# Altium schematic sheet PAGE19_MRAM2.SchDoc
size 381 x 381 mm; SheetNumber: 20; SheetTotal: 28
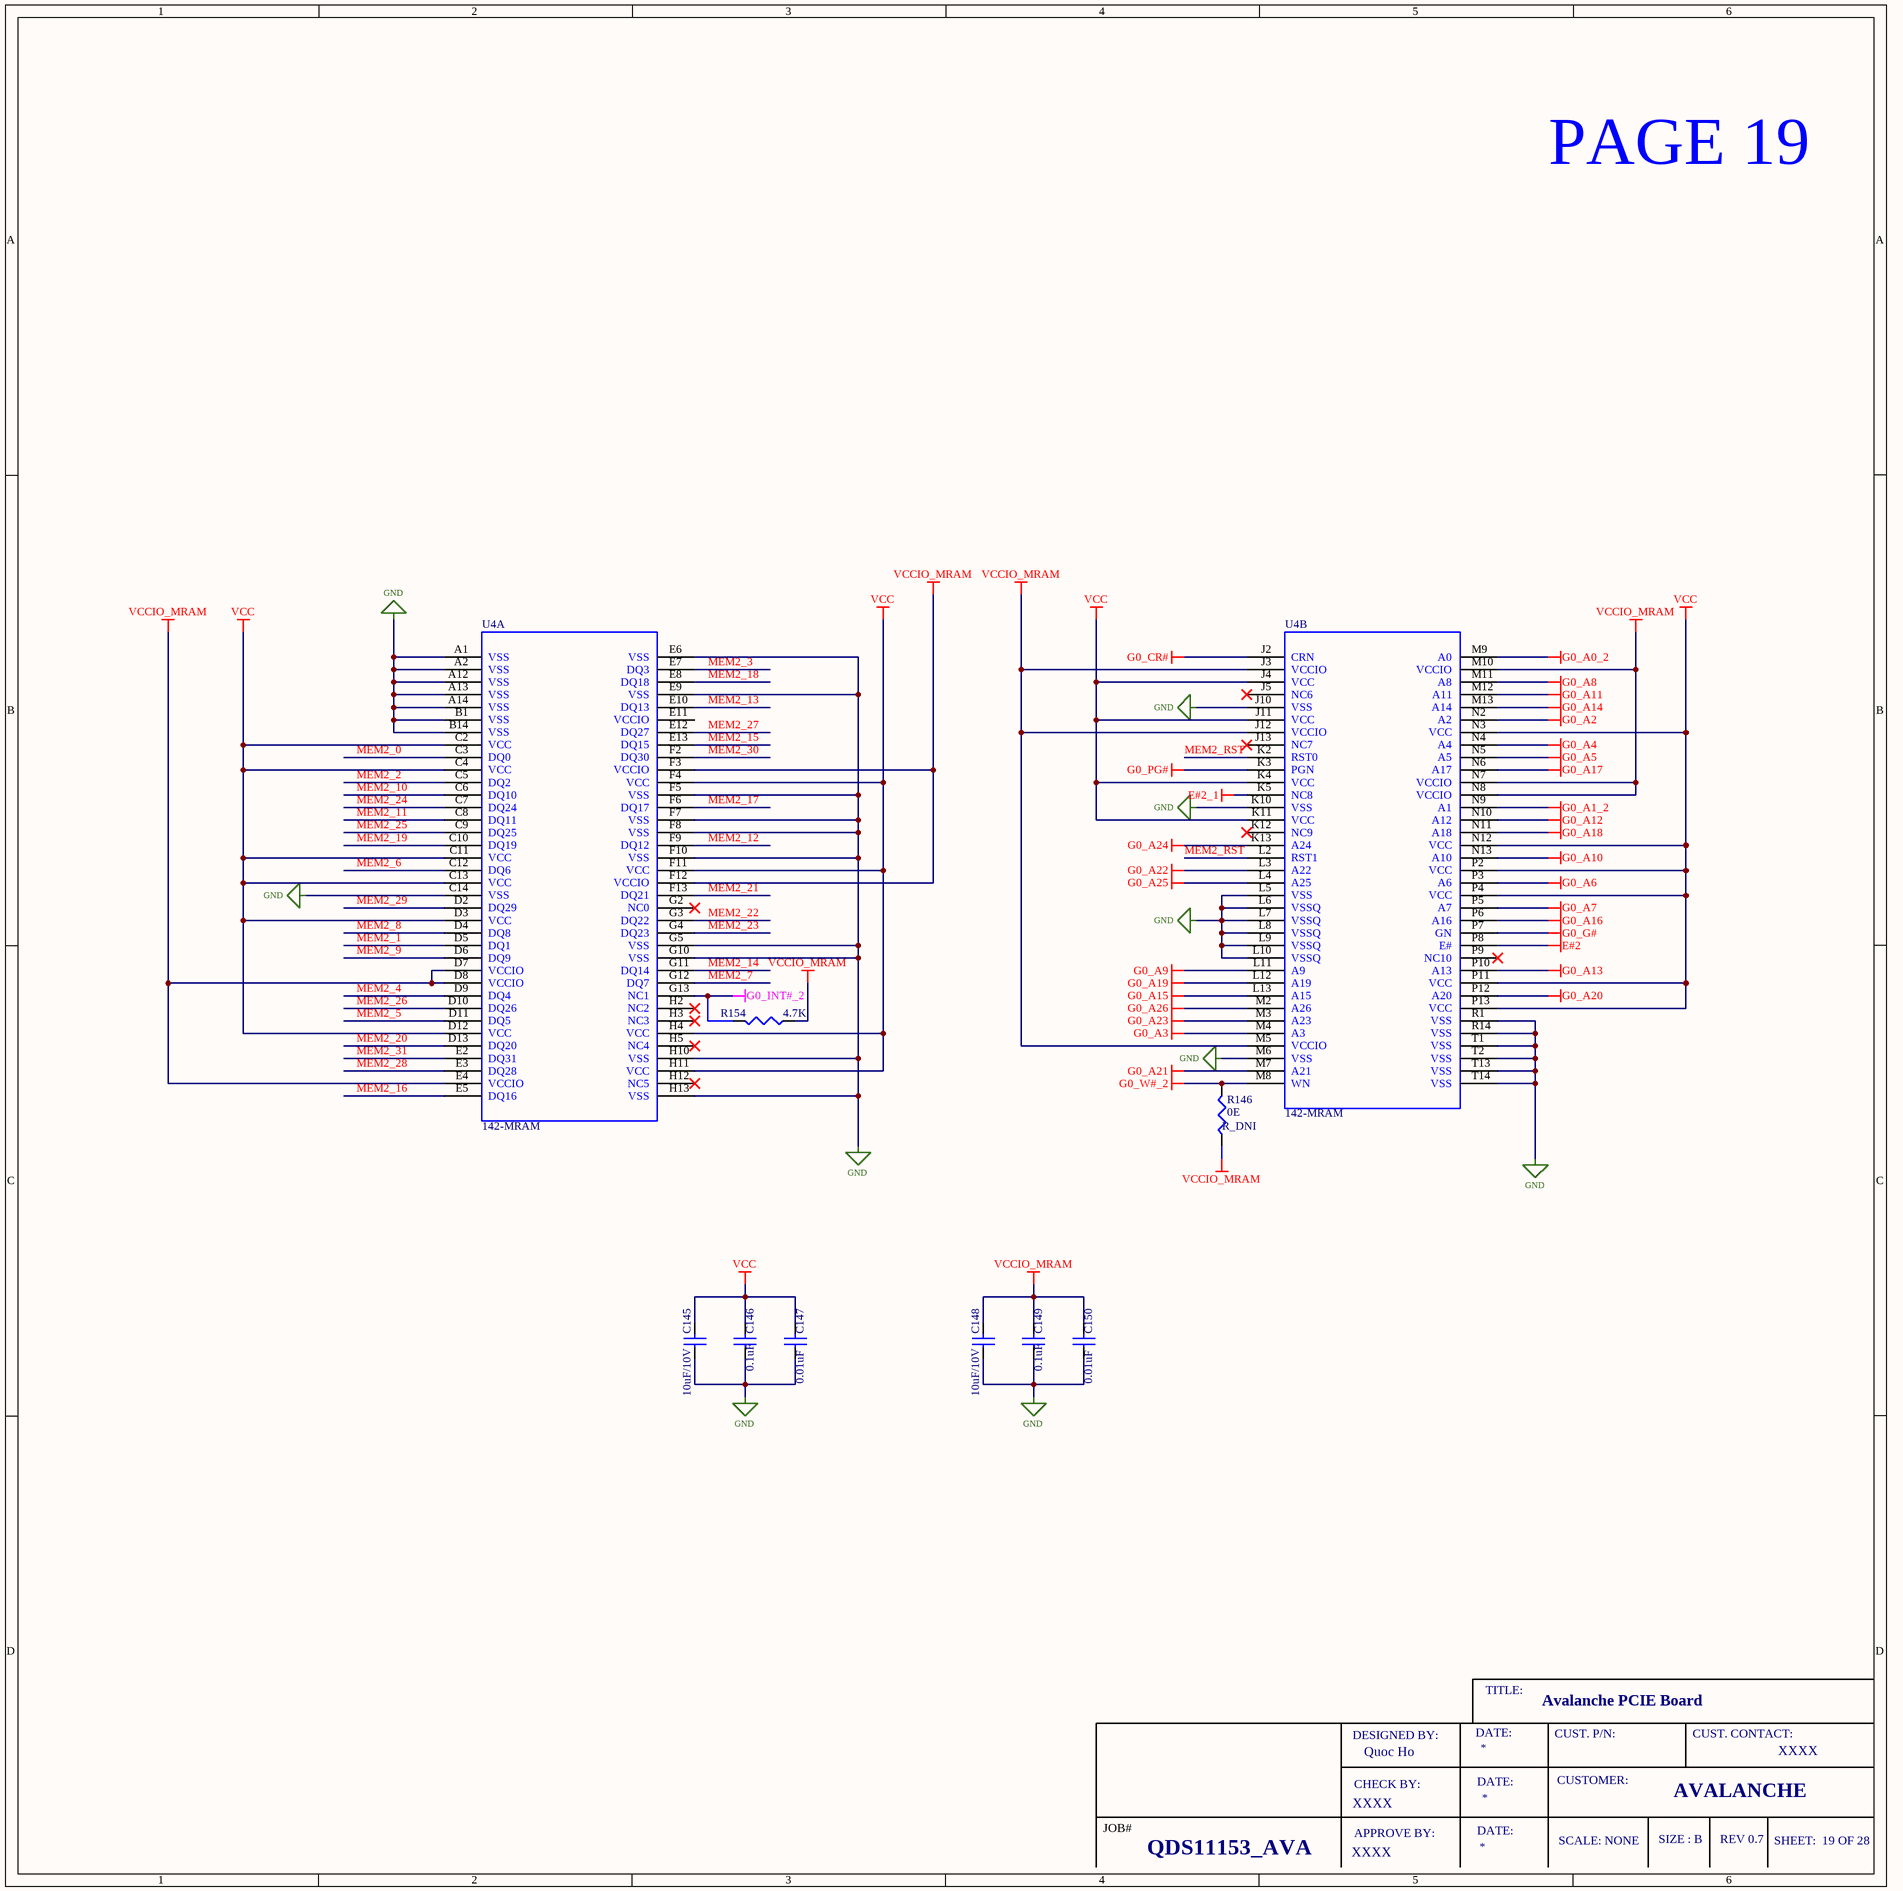
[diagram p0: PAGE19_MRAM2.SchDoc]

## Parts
C145  10uF/10V  [CN_0402]
C146  0.1uF  [CN_0402]
C147  0.01uF  [CN_0402]
C148  10uF/10V  [CN_0402]
C149  0.1uF  [CN_0402]
C150  0.01uF  [CN_0402]
R146  0E  [RN_0402]
R154  4.7K  [RN_0402]
U4  142-MRAM  [142-MRAM]  (parts A,B of 2)

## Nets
E#2: U4.P8(E#)
E#2_1: U4.K5(NC8)
G0_A0_2: U4.M9(A0)
G0_A1_2: U4.N9(A1)
G0_A2: U4.N2(A2)
G0_A3: U4.M4(A3)
G0_A4: U4.N4(A4)
G0_A5: U4.N5(A5)
G0_A6: U4.P3(A6)
G0_A7: U4.P5(A7)
G0_A8: U4.M11(A8)
G0_A9: U4.L11(A9)
G0_A10: U4.N13(A10)
G0_A11: U4.M12(A11)
G0_A12: U4.N10(A12)
G0_A13: U4.P10(A13)
G0_A14: U4.M13(A14)
G0_A15: U4.L13(A15)
G0_A16: U4.P6(A16)
G0_A17: U4.N6(A17)
G0_A18: U4.N11(A18)
G0_A19: U4.L12(A19)
G0_A20: U4.P12(A20)
G0_A21: U4.M7(A21)
G0_A22: U4.L3(A22)
G0_A23: U4.M3(A23)
G0_A24: U4.K13(A24)
G0_A25: U4.L4(A25)
G0_A26: U4.M2(A26)
G0_CR#: U4.J2(CRN)
G0_G#: U4.P7(GN)
G0_INT#_2: R154.2 U4.G13(NC1)
G0_PG#: U4.K3(PGN)
G0_W#_2: R146.2 U4.M8(WN)
GND: C145.1 C146.1 C147.1 C148.1 C149.1 C150.1 U4.A1(VSS) U4.A2(VSS) U4.A12(VSS) U4.A13(VSS) U4.A14(VSS) U4.B1(VSS) U4.B14(VSS) U4.C14(VSS) U4.E6(VSS) U4.E9(VSS) U4.F5(VSS) U4.F7(VSS) U4.F8(VSS) U4.F10(VSS) U4.G5(VSS) U4.G10(VSS) U4.H10(VSS) U4.H13(VSS) U4.J10(VSS) U4.K10(VSS) U4.L5(VSS) U4.L6(VSSQ) U4.L7(VSSQ) U4.L8(VSSQ) U4.L9(VSSQ) U4.L10(VSSQ) U4.M6(VSS) U4.R1(VSS) U4.R14(VSS) U4.T1(VSS) U4.T2(VSS) U4.T13(VSS) U4.T14(VSS)
VCC: C145.2 C146.2 C147.2 U4.C2(VCC) U4.C4(VCC) U4.C11(VCC) U4.C13(VCC) U4.D3(VCC) U4.D12(VCC) U4.F4(VCC) U4.F11(VCC) U4.H4(VCC) U4.H11(VCC) U4.J4(VCC) U4.J11(VCC) U4.K4(VCC) U4.K11(VCC) U4.N3(VCC) U4.N12(VCC) U4.P2(VCC) U4.P4(VCC) U4.P11(VCC) U4.P13(VCC)
VCCIO_MRAM: C148.2 C149.2 C150.2 R146.1 R154.1 U4.D7(VCCIO) U4.D8(VCCIO) U4.E4(VCCIO) U4.F3(VCCIO) U4.F12(VCCIO) U4.J3(VCCIO) U4.J12(VCCIO) U4.M5(VCCIO) U4.M10(VCCIO) U4.N7(VCCIO) U4.N8(VCCIO)
MEM2_0: U4.C3(DQ0)
MEM2_1: U4.D5(DQ1)
MEM2_2: U4.C5(DQ2)
MEM2_3: U4.E7(DQ3)
MEM2_4: U4.D9(DQ4)
MEM2_5: U4.D11(DQ5)
MEM2_6: U4.C12(DQ6)
MEM2_7: U4.G12(DQ7)
MEM2_8: U4.D4(DQ8)
MEM2_9: U4.D6(DQ9)
MEM2_10: U4.C6(DQ10)
MEM2_11: U4.C8(DQ11)
MEM2_12: U4.F9(DQ12)
MEM2_13: U4.E10(DQ13)
MEM2_14: U4.G11(DQ14)
MEM2_15: U4.E13(DQ15)
MEM2_16: U4.E5(DQ16)
MEM2_17: U4.F6(DQ17)
MEM2_18: U4.E8(DQ18)
MEM2_19: U4.C10(DQ19)
MEM2_20: U4.D13(DQ20)
MEM2_21: U4.F13(DQ21)
MEM2_22: U4.G3(DQ22)
MEM2_23: U4.G4(DQ23)
MEM2_24: U4.C7(DQ24)
MEM2_25: U4.C9(DQ25)
MEM2_26: U4.D10(DQ26)
MEM2_27: U4.E12(DQ27)
MEM2_28: U4.E3(DQ28)
MEM2_29: U4.D2(DQ29)
MEM2_30: U4.F2(DQ30)
MEM2_31: U4.E2(DQ31)
MEM2_RST: U4.K2(RST0) U4.L2(RST1)

Not connected (* = marked no-connect by the designer): U4 E11(VCCIO) G2(NC0)* H2(NC2)* H3(NC3)* H5(NC4)* H12(NC5)* J5(NC6)* J13(NC7)* K12(NC9)* P9(NC10)*

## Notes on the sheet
- PAGE 19
- TITLE:
- Avalanche PCIE Board
- DESIGNED BY:
- CHECK BY:
- Quoc Ho
- DATE:
- CUST. P/N:
- CUSTOMER:
- CUST. CONTACT:
- XXXX
- JOB#
- APPROVE BY:
- SCALE: NONE
- SIZE : B
- AVALANCHE
- REV 0.7
- SHEET:  19 OF 28
- QDS11153_AVA

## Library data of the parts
C145 C148 = CAP: CAP CER 10UF 10V X5R 0402; Manufacturer Part Number: GRM155R61A106ME11D; Manufacturer: Murata Electronics
C146 C149 = CAP: CAP CER 0.1UF 50V X7R 0402; Manufacturer Part Number: GCM155R71H104KE02J; Manufacturer: Murata Electronics
C147 C150 = CAP: 0.01 µF, 25 V, 0402 [1005 Metric], ± 10%, X7R; Manufacturer Part Number: CC0402JRX7R8BB103; Manufacturer: YAGEO
R146 = RES: RES 0 OHM JUMPER 1/16W 0402; Manufacturer Part Number: RC0402FR-070RL; Manufacturer: YAGEO
R154 = RES: RES 4.7K OHM 1% 1/16W 0402; Manufacturer Part Number: RC0402FR-134K7L; Manufacturer: YAGEO
U4 = 142-MRAM: IC 142-MRAM MEMORY; Manufacturer: Avalanche Technology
